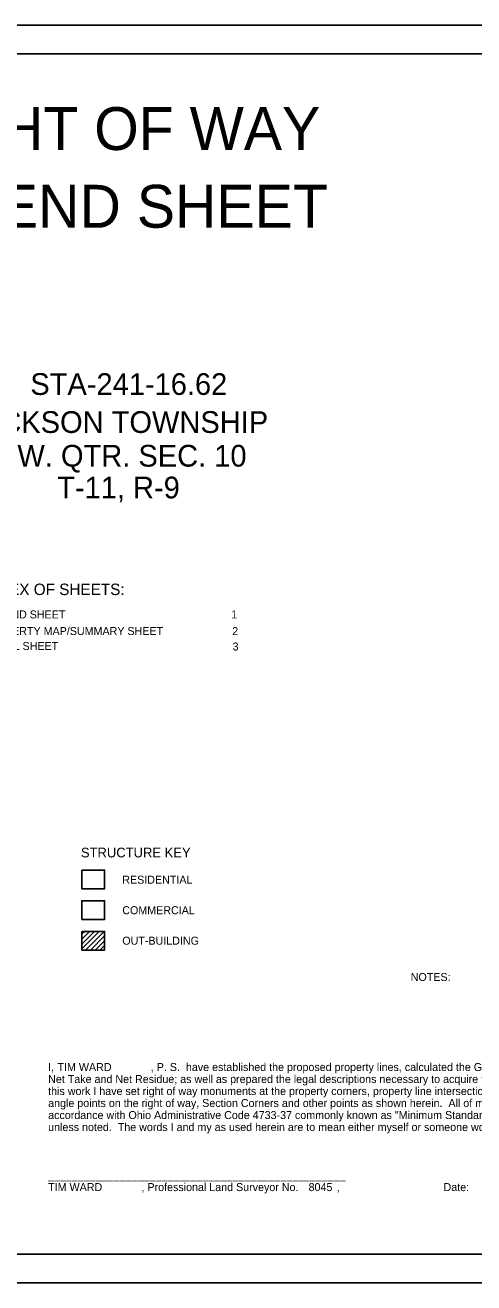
# Model space of a CAD drawing. Extents: x 0 to 34, y 0 to 22.
# Drawn here: x 14.42 to 22.27, y 0 to 22 of the extents above; entities that cross this region are included whole.
import ezdxf

# ---------------------------------------------------------------- set-up
doc = ezdxf.new("R2010")
doc.units = 0
for name, color, linetype in [('SC_Shading1', 7, 'Continuous'), ('SH_Border', 7, 'Continuous'), ('SH_Cut_Line', 7, 'Continuous'), ('SH_Data', 7, 'Continuous'), ('SH_Text', 7, 'Continuous')]:
    doc.layers.add(name, color=color, linetype=linetype)

msp = doc.modelspace()

# ---------------------------------------------------------------- linework, layer by layer
at = {"layer": 'SC_Shading1'}
msp.add_lwpolyline([(15.408, 6.357), (15.806, 6.357), (15.806, 6.683), (15.408, 6.683)], close=True, dxfattribs=at)
at = {"layer": 'SH_Border'}
msp.add_lwpolyline([(1.5, 21.5), (33.5, 21.5), (33.5, 0.5), (1.5, 0.5)], close=True, dxfattribs=at)
at = {"layer": 'SH_Cut_Line'}
msp.add_lwpolyline([(0, 0), (34, 0), (34, 22), (0, 22)], close=True, dxfattribs=at)
at = {"layer": 'SH_Text'}
for p, q in [((15.408, 6.147), (15.41, 6.148)), ((15.408, 6.097), (15.46, 6.148)), ((15.408, 6.012), (15.545, 6.148)), ((15.408, 5.927), (15.629, 6.148)), ((15.408, 5.842), (15.714, 6.148)), ((15.473, 5.822), (15.799, 6.148)), ((15.558, 5.822), (15.806, 6.07)), ((15.642, 5.822), (15.806, 5.985)), ((15.408, 5.827), (15.413, 5.822)), ((15.727, 5.822), (15.806, 5.901))]:
    msp.add_line(p, q, dxfattribs=at)
for points in [[(15.408, 7.219), (15.806, 7.219), (15.806, 6.893), (15.408, 6.893)], [(15.408, 6.148), (15.806, 6.148), (15.806, 5.822), (15.408, 5.822)]]:
    msp.add_lwpolyline(points, close=True, dxfattribs=at)

# ---------------------------------------------------------------- texts
at = {"layer": 'SH_Data'}
for s, height, p in [('RIGHT OF WAY', 0.75, (12.227, 19.816)), ('LEGEND SHEET', 0.75, (11.968, 18.457)), ('STA-241-16.62', 0.38, (14.508, 15.532)), ('JACKSON TOWNSHIP', 0.38, (13.39, 14.867)), ('N.W. QTR. SEC. 10', 0.38, (13.774, 14.278)), ('T-11, R-9', 0.38, (14.978, 13.722)), ('INDEX OF SHEETS:', 0.2, (13.676, 12.031)), ('LEGEND SHEET                       ', 0.14, (13.676, 11.622)), ('1     ', 0.14, (18.022, 11.622)), ('PROPERTY MAP/SUMMARY SHEET', 0.14, (13.659, 11.332)), ('2', 0.14, (18.041, 11.33)), ('DETAIL SHEET', 0.14, (13.664, 11.07)), ('3', 0.14, (18.048, 11.061))]:
    msp.add_text(s, height=height, dxfattribs=at).set_placement(p)
at = {"layer": 'SH_Text'}
for s, height, p in [('STRUCTURE KEY', 0.17, (15.393, 7.442)), ('RESIDENTIAL', 0.14, (16.117, 6.982)), ('COMMERCIAL', 0.14, (16.117, 6.448)), ('OUT-BUILDING', 0.14, (16.117, 5.915)), ('NOTES:', 0.14, (21.164, 5.28)), ('I, ', 0.14, (14.82, 3.705)), ('TIM WARD            ', 0.14, (14.983, 3.705)), (', P. S.  have established the proposed property lines, calculated the Gross Take, Present Roadway Occupied (PRO),', 0.14, (16.616, 3.705)), ('Net Take and Net Residue; as well as prepared the legal descriptions necessary to acquire these parcels as shown herein. As a part of', 0.14, (14.82, 3.495)), ('this work I have set right of way monuments at the property corners, property line intersections, points along the right of way and/or', 0.14, (14.82, 3.285)), ('angle points on the right of way, Section Corners and other points as shown herein.  All of my work contained herein was conducted in', 0.14, (14.82, 3.075)), ('accordance with Ohio Administrative Code 4733-37 commonly known as "Minimum Standards for Boundary Surveys in the State of Ohio"', 0.14, (14.82, 2.865)), ('unless noted.  The words I and my as used herein are to mean either myself or someone working under my direct supervision.', 0.14, (14.82, 2.655)), ('__________________________________________________', 0.14, (14.82, 1.815)), ('TIM WARD            ', 0.14, (14.82, 1.605)), (', Professional Land Surveyor No. ', 0.14, (16.453, 1.605)), ('8045 ', 0.14, (19.377, 1.605)), (',                                   Date: ', 0.14, (19.866, 1.605))]:
    msp.add_text(s, height=height, dxfattribs=at).set_placement(p)

doc.saveas('drawing.dxf')
